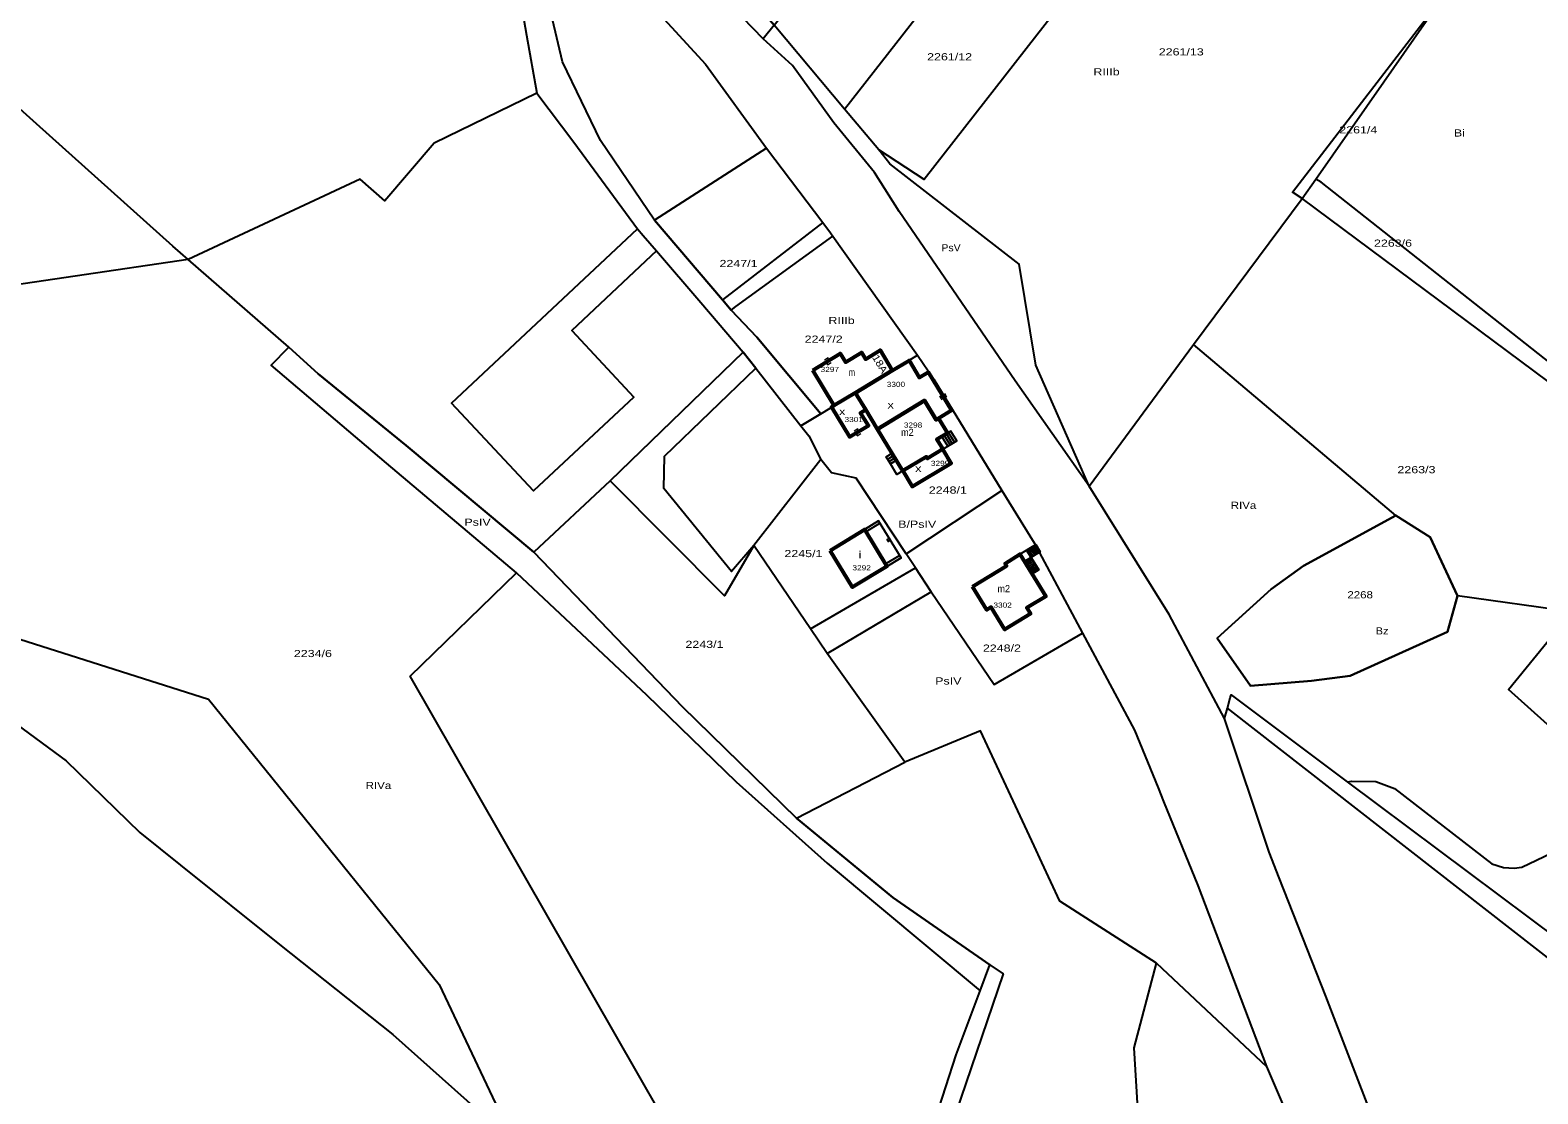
# Model space of a CAD drawing. Extents: x 4641351 to 4644672, y 5357112 to 5362385.
# Drawn here: x 4642629.6 to 4642892.9, y 5358310.3 to 5358496 of the extents above; entities that cross this region are included whole.
import ezdxf
from ezdxf.enums import TextEntityAlignment as Align

# ---------------------------------------------------------------- set-up
doc = ezdxf.new("R2010")
doc.units = 0
doc.header["$LTSCALE"] = 0.5
for name, color, linetype in [('1', 7, 'Continuous'), ('24', 7, 'Continuous'), ('26', 7, 'Continuous'), ('4', 7, 'Continuous')]:
    doc.layers.add(name, color=color, linetype=linetype)
for name, color, linetype, lineweight in [('12', 7, 'Continuous', 25), ('15', 7, 'Continuous', 25), ('2', 7, 'Continuous', 25), ('25', 7, 'Continuous', 25), ('27', 7, 'Continuous', 25), ('3', 7, 'Continuous', 13)]:
    doc.layers.add(name, color=color, linetype=linetype, lineweight=lineweight)

msp = doc.modelspace()

# ---------------------------------------------------------------- linework, layer by layer
at = {"layer": '12'}
msp.add_lwpolyline([(4642779.191, 5358402.345), (4642781.659, 5358403.849), (4642777.73, 5358410.295), (4642775.262, 5358408.791)], close=True, dxfattribs=at)
at = {"layer": '15'}
for p, q in [((4642790.206, 5358423.556), (4642789.179, 5358425.256)), ((4642790.593, 5358423.79), (4642789.566, 5358425.49)), ((4642790.98, 5358424.024), (4642789.952, 5358425.724)), ((4642789.819, 5358423.322), (4642788.792, 5358425.022)), ((4642779.312, 5358421.055), (4642780.346, 5358421.681)), ((4642779.557, 5358420.652), (4642780.59, 5358421.277)), ((4642804.359, 5358403.893), (4642803.571, 5358405.176)), ((4642804.679, 5358404.09), (4642803.891, 5358405.373)), ((4642804.999, 5358404.286), (4642804.211, 5358405.569)), ((4642805.319, 5358404.482), (4642804.531, 5358405.766)), ((4642805.64, 5358404.68), (4642804.852, 5358405.963)), ((4642803.377, 5358402.866), (4642804.548, 5358403.585)), ((4642803.566, 5358402.558), (4642804.737, 5358403.277)), ((4642803.756, 5358402.25), (4642804.927, 5358402.969)), ((4642803.945, 5358401.941), (4642805.116, 5358402.66)), ((4642804.135, 5358401.633), (4642805.305, 5358402.352)), ((4642804.324, 5358401.325), (4642805.494, 5358402.044))]:
    msp.add_line(p, q, dxfattribs=at)
for points in [[(4642788.945, 5358422.794), (4642791.367, 5358424.258), (4642790.339, 5358425.958), (4642787.917, 5358424.494)], [(4642780.834, 5358420.873), (4642779.801, 5358420.248), (4642779.068, 5358421.459), (4642780.101, 5358422.084)], [(4642781.947, 5358419.034), (4642780.914, 5358418.409), (4642779.801, 5358420.248), (4642780.834, 5358420.873)], [(4642802.4, 5358404.457), (4642805.172, 5358406.159), (4642805.96, 5358404.876), (4642803.188, 5358403.174)], [(4642804.359, 5358403.893), (4642805.684, 5358401.736), (4642804.513, 5358401.017), (4642803.188, 5358403.174)]]:
    msp.add_lwpolyline(points, close=True, dxfattribs=at)
at = {"layer": '2'}
for points in [[(4642775.262, 5358408.791), (4642777.73, 5358410.295), (4642777.99, 5358409.868), (4642775.522, 5358408.365)], [(4642779.582, 5358407.256), (4642779.24, 5358407.048), (4642779.448, 5358406.706), (4642779.79, 5358406.914)], [(4642778.93, 5358402.773), (4642781.399, 5358404.276), (4642781.659, 5358403.849), (4642779.191, 5358402.345)]]:
    msp.add_lwpolyline(points, close=True, dxfattribs=at)
at = {"layer": '25'}
for p, q in [((4642771.768, 5358482.173), (4642795.74, 5358512.81)), ((4642758.15, 5358475.359), (4642738.615, 5358462.808)), ((4642767.651, 5358428.998), (4642764.171, 5358426.892)), ((4642782.546, 5358404.534), (4642799.272, 5358415.573))]:
    msp.add_line(p, q, dxfattribs=at)
for points in [[(4642814.499, 5358416.375), (4642832.69, 5358441.11), (4642851.665, 5358466.546), (4642849.999, 5358467.681), (4642876.813, 5358502.594), (4642876.065, 5358503.034), (4642869.493, 5358508.287), (4642840.29, 5358531), (4642818.337, 5358548.076), (4642796.194, 5358519.772), (4642782.423, 5358533.986), (4642779.151, 5358529.964)], [(4642756.132, 5358500.785), (4642759.482, 5358496.805), (4642779.53, 5358522.144), (4642781.821, 5358523.415), (4642783.837, 5358523.555), (4642786.699, 5358522.288), (4642795.74, 5358512.81), (4642808.702, 5358499.305), (4642785.703, 5358469.897), (4642777.754, 5358475.055), (4642771.768, 5358482.173), (4642759.482, 5358496.805), (4642757.593, 5358494.469)], [(4642735.609, 5358502.997), (4642747.521, 5358490.039), (4642758.15, 5358475.359), (4642767.969, 5358462.356), (4642769.301, 5358460.592), (4642769.715, 5358460.008), (4642784.527, 5358439.212), (4642787.355, 5358435.006), (4642799.272, 5358415.573), (4642804.867, 5358406.449), (4642813.341, 5358390.662), (4642822.412, 5358373.764), (4642826.529, 5358363.675), (4642827.488, 5358361.324), (4642833.477, 5358346.646), (4642845.491, 5358315.046), (4642858.502, 5358284.577)], [(4642851.665, 5358466.546), (4642854.067, 5358469.965), (4642865.977, 5358486.915), (4642876.813, 5358502.594)], [(4642845.909, 5358352.44), (4642838.15, 5358375.797), (4642828.497, 5358393.941), (4642814.499, 5358416.375), (4642801.572, 5358434.757), (4642781.331, 5358464.31), (4642776.99, 5358471.083), (4642769.921, 5358479.808), (4642762.681, 5358489.787), (4642757.593, 5358494.469), (4642754.026, 5358498.12)], [(4642771.436, 5358255.602), (4642791.286, 5358317.1), (4642795.459, 5358328.226), (4642797.177, 5358332.807), (4642780.193, 5358344.531), (4642763.404, 5358358.398), (4642743.456, 5358377.851), (4642717.527, 5358404.849), (4642695.236, 5358423.477), (4642679.869, 5358435.96), (4642674.736, 5358440.608), (4642657.178, 5358455.898), (4642654.456, 5358458.268), (4642630.681, 5358479.602), (4642614.862, 5358493.797)], [(4642949.553, 5358417.948), (4642948.79, 5358418.68), (4642938.16, 5358404.01), (4642915.98, 5358421.35), (4642911.44, 5358424.9), (4642880.75, 5358449.12), (4642855.04, 5358469.41), (4642854.067, 5358469.965)], [(4642838.15, 5358375.797), (4642838.628, 5358377.587), (4642839.108, 5358379.387), (4642839.29, 5358379.904), (4642859.576, 5358364.742), (4642901.918, 5358333.096), (4642922.577, 5358358.199), (4642924.925, 5358361.574), (4642934.723, 5358373.188), (4642941.631, 5358381.377), (4642946.63, 5358387.84), (4642949.327, 5358390.688), (4642958.54, 5358403.51), (4642960.298, 5358405.672), (4642962.716, 5358408.645), (4642952.606, 5358421.843), (4642949.553, 5358417.948), (4642937.604, 5358402.701), (4642851.665, 5358466.546)], [(4642738.615, 5358462.808), (4642750.449, 5358448.892), (4642751.975, 5358447.098), (4642752.821, 5358447.722), (4642769.715, 5358460.008)], [(4642751.975, 5358447.098), (4642756.464, 5358442.383), (4642767.651, 5358428.998), (4642784.527, 5358439.212)], [(4642763.404, 5358358.398), (4642782.312, 5358368.175), (4642768.739, 5358387.136), (4642765.807, 5358391.449), (4642755.936, 5358405.97), (4642752.044, 5358401.447), (4642740.252, 5358415.933), (4642740.355, 5358421.571), (4642756.272, 5358436.949), (4642754.098, 5358439.718), (4642730.873, 5358417.275), (4642717.527, 5358404.849)], [(4642764.171, 5358426.892), (4642765.553, 5358425.132), (4642767.628, 5358420.992)], [(4642768.739, 5358387.136), (4642786.923, 5358397.922), (4642784.143, 5358402.122), (4642782.546, 5358404.534), (4642773.79, 5358417.764), (4642769.49, 5358418.684), (4642767.628, 5358420.992), (4642755.936, 5358405.97)], [(4642786.923, 5358397.922), (4642797.898, 5358381.741), (4642813.341, 5358390.662)], [(4642612.803, 5358385.36), (4642635.877, 5358368.389), (4642648.715, 5358355.875), (4642655.84, 5358350.162), (4642673.111, 5358336.329), (4642692.883, 5358320.629), (4642707.989, 5358307.194)], [(4642868.421, 5358294.647), (4642855.823, 5358327.307), (4642847.693, 5358347.957), (4642845.909, 5358352.44)]]:
    msp.add_lwpolyline(points, dxfattribs=at)
msp.add_lwpolyline([(4642836.827, 5358389.798), (4642842.654, 5358381.515), (4642853.337, 5358382.388), (4642860.091, 5358383.224), (4642877.084, 5358390.907), (4642878.814, 5358397.188), (4642874.05, 5358407.458), (4642868.048, 5358411.256), (4642851.932, 5358402.432), (4642846.306, 5358398.365)], close=True, dxfattribs=at)
at = {"layer": '27'}
for p, q in [((4642767.969, 5358462.356), (4642750.449, 5358448.892)), ((4642767.651, 5358428.998), (4642784.527, 5358439.212)), ((4642826.23, 5358333.06), (4642845.491, 5358315.046))]:
    msp.add_line(p, q, dxfattribs=at)
for points in [[(4642814.499, 5358416.375), (4642832.69, 5358441.11), (4642851.665, 5358466.546), (4642854.067, 5358469.965), (4642865.977, 5358486.915), (4642876.813, 5358502.594), (4642876.065, 5358503.034), (4642869.493, 5358508.287), (4642840.29, 5358531), (4642818.337, 5358548.076), (4642803.325, 5358560.279), (4642821.598, 5358584.001), (4642816.06, 5358588.317), (4642814.041, 5358585.727), (4642802.267, 5358594.9)], [(4642868.421, 5358294.647), (4642855.823, 5358327.307), (4642847.693, 5358347.957), (4642845.909, 5358352.44), (4642838.15, 5358375.797), (4642828.497, 5358393.941), (4642814.499, 5358416.375), (4642801.572, 5358434.757), (4642781.331, 5358464.31), (4642776.99, 5358471.083), (4642769.921, 5358479.808), (4642762.681, 5358489.787), (4642757.593, 5358494.469), (4642754.026, 5358498.12), (4642742.919, 5358510.01), (4642740.118, 5358513.008), (4642723.918, 5358529.947)], [(4642738.615, 5358462.808), (4642729.148, 5358476.722), (4642722.529, 5358490.401), (4642716.298, 5358516.833), (4642716.233, 5358522.576), (4642735.609, 5358502.997), (4642747.521, 5358490.039), (4642758.15, 5358475.359), (4642767.969, 5358462.356), (4642769.301, 5358460.592), (4642769.715, 5358460.008), (4642784.527, 5358439.212), (4642787.355, 5358435.006), (4642799.272, 5358415.573), (4642804.867, 5358406.449), (4642813.341, 5358390.662), (4642822.412, 5358373.764), (4642826.529, 5358363.675), (4642827.488, 5358361.324), (4642833.477, 5358346.646), (4642845.491, 5358315.046), (4642858.502, 5358284.577)], [(4642814.499, 5358416.375), (4642805.197, 5358437.487), (4642802.251, 5358455.107), (4642779.697, 5358472.597), (4642777.754, 5358475.055), (4642771.768, 5358482.173), (4642759.482, 5358496.805), (4642756.132, 5358500.785), (4642746.404, 5358514.456)], [(4642715.318, 5358500.411), (4642716.258, 5358495.075), (4642718.04, 5358484.962), (4642724.478, 5358476.407), (4642735.645, 5358461.25), (4642736.621, 5358460.108), (4642738.919, 5358457.427), (4642746.664, 5358448.392), (4642754.098, 5358439.718), (4642756.272, 5358436.949), (4642764.171, 5358426.892), (4642767.651, 5358428.998), (4642756.464, 5358442.383), (4642751.975, 5358447.098), (4642750.449, 5358448.892), (4642738.615, 5358462.808)], [(4642718.04, 5358484.962), (4642700.122, 5358476.237), (4642691.487, 5358466.155), (4642687.205, 5358469.964), (4642657.178, 5358455.898), (4642597.88, 5358447.21), (4642597.79, 5358446.98), (4642589.75, 5358425.62), (4642583.35, 5358408.62), (4642582.886, 5358407.4)], [(4642898.811, 5358394.432), (4642902.777, 5358399.279), (4642910.723, 5358392.789), (4642946.63, 5358387.84), (4642949.327, 5358390.688), (4642958.54, 5358403.51), (4642960.298, 5358405.672), (4642962.716, 5358408.645), (4642976.441, 5358423.831), (4642978.909, 5358426.777), (4643001.999, 5358404.318), (4643011.786, 5358415.655), (4642953.64, 5358457.32), (4642937.011, 5358439.641), (4642950.281, 5358424.879), (4642952.606, 5358421.843), (4642949.553, 5358417.948), (4642948.79, 5358418.68), (4642938.16, 5358404.01), (4642915.98, 5358421.35), (4642911.44, 5358424.9), (4642880.75, 5358449.12), (4642855.04, 5358469.41), (4642854.067, 5358469.965)], [(4642738.919, 5358457.427), (4642724.152, 5358443.525), (4642735.009, 5358431.91), (4642717.474, 5358415.52), (4642703.135, 5358430.86), (4642735.645, 5358461.25)], [(4642853.337, 5358382.388), (4642842.654, 5358381.515), (4642836.827, 5358389.798), (4642846.306, 5358398.365), (4642851.932, 5358402.432), (4642868.048, 5358411.256), (4642832.69, 5358441.11)], [(4642767.511, 5358258.211), (4642695.938, 5358383.164), (4642714.505, 5358401.203), (4642691.817, 5358420.385), (4642671.679, 5358437.497), (4642674.736, 5358440.608), (4642679.869, 5358435.96), (4642695.236, 5358423.477), (4642717.527, 5358404.849), (4642743.456, 5358377.851), (4642763.404, 5358358.398), (4642780.193, 5358344.531), (4642797.177, 5358332.807), (4642799.473, 5358331.222), (4642773.543, 5358254.963)], [(4642823.339, 5358301.932), (4642822.339, 5358318.284), (4642826.23, 5358333.06), (4642809.362, 5358343.926), (4642806.237, 5358350.642), (4642804.892, 5358353.533), (4642795.529, 5358373.657), (4642782.312, 5358368.175), (4642768.739, 5358387.136), (4642765.807, 5358391.449), (4642755.936, 5358405.97), (4642750.821, 5358397.181), (4642730.873, 5358417.275), (4642754.098, 5358439.718)], [(4642764.171, 5358426.892), (4642765.553, 5358425.132), (4642767.628, 5358420.992), (4642755.936, 5358405.97)], [(4642765.807, 5358391.449), (4642784.143, 5358402.122), (4642782.546, 5358404.534), (4642799.272, 5358415.573)], [(4642868.048, 5358411.256), (4642874.05, 5358407.458), (4642878.814, 5358397.188)], [(4642590.89, 5358401.343), (4642660.722, 5358379.156), (4642700.966, 5358329.335), (4642713.896, 5358302.071)], [(4642714.505, 5358401.203), (4642737.17, 5358379.946), (4642752.878, 5358364.715), (4642768.759, 5358350.529), (4642795.459, 5358328.226), (4642797.177, 5358332.807)], [(4642952.275, 5358288.364), (4642923.143, 5358312.935), (4642897.419, 5358331.781), (4642838.628, 5358377.587), (4642839.108, 5358379.387), (4642839.29, 5358379.904), (4642859.576, 5358364.742), (4642860.374, 5358364.875), (4642864.53, 5358364.78), (4642867.79, 5358363.588), (4642884.824, 5358350.424), (4642886.871, 5358349.775), (4642888.726, 5358349.688), (4642890.08, 5358349.862), (4642897.74, 5358353.517), (4642894.991, 5358356.21), (4642901.859, 5358368.18), (4642887.707, 5358380.858), (4642898.811, 5358394.432), (4642878.814, 5358397.188), (4642877.084, 5358390.907), (4642860.091, 5358383.224), (4642853.337, 5358382.388)]]:
    msp.add_lwpolyline(points, dxfattribs=at)
at = {"layer": '3'}
for p, q in [((4642768.283, 5358438.408), (4642768.925, 5358438.796)), ((4642768.801, 5358437.552), (4642768.925, 5358438.796)), ((4642768.801, 5358437.552), (4642769.443, 5358437.94)), ((4642788.354, 5358432.081), (4642788.742, 5358431.439)), ((4642788.354, 5358432.081), (4642789.598, 5358431.957)), ((4642789.21, 5358432.599), (4642789.598, 5358431.957)), ((4642773.46, 5358426.005), (4642774.102, 5358426.393)), ((4642773.978, 5358425.149), (4642774.102, 5358426.393)), ((4642773.978, 5358425.149), (4642774.62, 5358425.537))]:
    msp.add_line(p, q, dxfattribs=at)
at = {"layer": '3', "lineweight": 53}
for points in [[(4642766.242, 5358436.587), (4642771.035, 5358439.488), (4642771.931, 5358438.007), (4642774.715, 5358439.691), (4642775.413, 5358438.537), (4642777.978, 5358440.09), (4642780.123, 5358436.546), (4642773.702, 5358432.661), (4642769.981, 5358430.408)], [(4642773.702, 5358432.661), (4642780.123, 5358436.546), (4642783.037, 5358438.308), (4642784.84, 5358435.326), (4642786.404, 5358436.272), (4642790.473, 5358429.543), (4642788.208, 5358428.173), (4642787.788, 5358427.919), (4642785.755, 5358431.28), (4642777.543, 5358426.313), (4642775.487, 5358429.712)], [(4642769.981, 5358430.408), (4642769.527, 5358430.133), (4642772.669, 5358424.941), (4642775.946, 5358426.925), (4642774.588, 5358429.168), (4642775.487, 5358429.712), (4642773.702, 5358432.661)], [(4642777.543, 5358426.313), (4642785.755, 5358431.28), (4642787.788, 5358427.919), (4642788.208, 5358428.173), (4642789.76, 5358425.607), (4642787.918, 5358424.493), (4642788.932, 5358422.816), (4642786.246, 5358421.192), (4642786.072, 5358421.48), (4642781.967, 5358419)], [(4642781.967, 5358419), (4642783.611, 5358416.283), (4642790.4, 5358420.39), (4642788.932, 5358422.816), (4642786.246, 5358421.192), (4642786.072, 5358421.48)], [(4642769.267, 5358405.137), (4642775.262, 5358408.791), (4642779.191, 5358402.345), (4642773.197, 5358398.691)], [(4642794.124, 5358398.828), (4642800.062, 5358402.465), (4642799.814, 5358402.869), (4642802.4, 5358404.457), (4642806.911, 5358397.111), (4642803.627, 5358395.094), (4642804.255, 5358394.072), (4642799.751, 5358391.304), (4642797.356, 5358395.201), (4642796.627, 5358394.753)]]:
    msp.add_lwpolyline(points, close=True, dxfattribs=at)

# ---------------------------------------------------------------- texts
at = {"layer": '1', "width": 1.15}
msp.add_text('18A', height=1.25, rotation=301.181, dxfattribs=at).set_placement((4642777.432, 5358437.372), align=Align.CENTER)
at = {"layer": '24'}
for s, width, p in [('2261/12', 1.3, (4642786.201, 5358490.69)), ('2261/13', 1.3, (4642826.651, 5358491.543)), ('2261/4', 1.3, (4642858.174, 5358477.93)), ('2263/6', 1.3, (4642864.233, 5358458.154)), ('2247/1', 1.3, (4642749.942, 5358454.602)), ('2247/2', 1.3, (4642764.811, 5358441.392)), ('2263/3', 1.3, (4642868.329, 5358418.608)), ('2248/1', 1.3, (4642786.494, 5358415.045)), ('2245/1', 1.3, (4642761.278, 5358403.962)), ('2268', 1.2, (4642859.587, 5358396.767)), ('2243/1', 1.3, (4642743.997, 5358388.109)), ('2248/2', 1.3, (4642795.942, 5358387.456)), ('2234/6', 1.3, (4642675.616, 5358386.512))]:
    msp.add_text(s, height=1.25, dxfattribs=dict(at, width=width)).set_placement(p)
at = {"layer": '26'}
for s, width, p in [('RIIIb', 1.3, (4642815.234, 5358488.072)), ('Bi', 1.3, (4642878.19, 5358477.39)), ('PsV', 1.1, (4642788.69, 5358457.345)), ('RIIIb', 1.3, (4642768.964, 5358444.651)), ('RIVa', 1.2, (4642839.223, 5358412.386)), ('PsIV', 1.3, (4642705.395, 5358409.434)), ('B/PsIV', 1.3, (4642781.151, 5358409.083)), ('Bz', 1.15, (4642864.529, 5358390.457)), ('PsIV', 1.3, (4642787.607, 5358381.72)), ('RIVa', 1.2, (4642688.16, 5358363.478))]:
    msp.add_text(s, height=1.25, dxfattribs=dict(at, width=width)).set_placement(p)
at = {"layer": '4', "width": 1.2}
for s, p in [('3297', (4642767.6, 5358436.28)), ('3300', (4642779.153, 5358433.675)), ('3301', (4642771.777, 5358427.542)), ('3298', (4642782.137, 5358426.565)), ('3299', (4642786.856, 5358419.889)), ('3292', (4642773.163, 5358401.655)), ('3302', (4642797.781, 5358395.133))]:
    msp.add_text(s, height=0.9, dxfattribs=at).set_placement(p)
at = {"layer": '4'}
for s, width, p in [('m', 0.8, (4642773.059, 5358435.593)), ('x', 1.3, (4642779.836, 5358429.906)), ('x', 1.3, (4642771.374, 5358428.766)), ('m2', 0.95, (4642782.756, 5358425.125)), ('x', 1.3, (4642784.663, 5358418.833)), ('i', 1.3, (4642774.473, 5358403.756)), ('m2', 0.95, (4642799.578, 5358397.831))]:
    msp.add_text(s, height=1.25, dxfattribs=dict(at, width=width)).set_placement(p, align=Align.CENTER)

doc.saveas('drawing.dxf')
